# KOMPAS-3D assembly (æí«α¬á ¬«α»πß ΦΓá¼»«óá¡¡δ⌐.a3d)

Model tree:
1. Эскиз:1
2. Вырезать элемент выдавливания:1
     Расстояние 1 = 133.122
3. Вырезать элемент выдавливания:3  (labels: Сплав АЛ8  ГОСТ 1583-93)
     Расстояние 1 = 133.122; Ориентация = 2

Referenced files in D:\МОДЕЛЬ ТАНКА Т90\ДЕТАЛИ\КОРПУС\МЕТАЛЛ\КОРПУС ШТАМПОВКА\: ванна.m3d, наружняя накладка борта.m3d, ступица балансира.m3d, ступица балансира1.m3d, дно2 скос .m3d
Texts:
  Сборка корпус штампованный
  Сплав АЛ8  ГОСТ 1583-93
